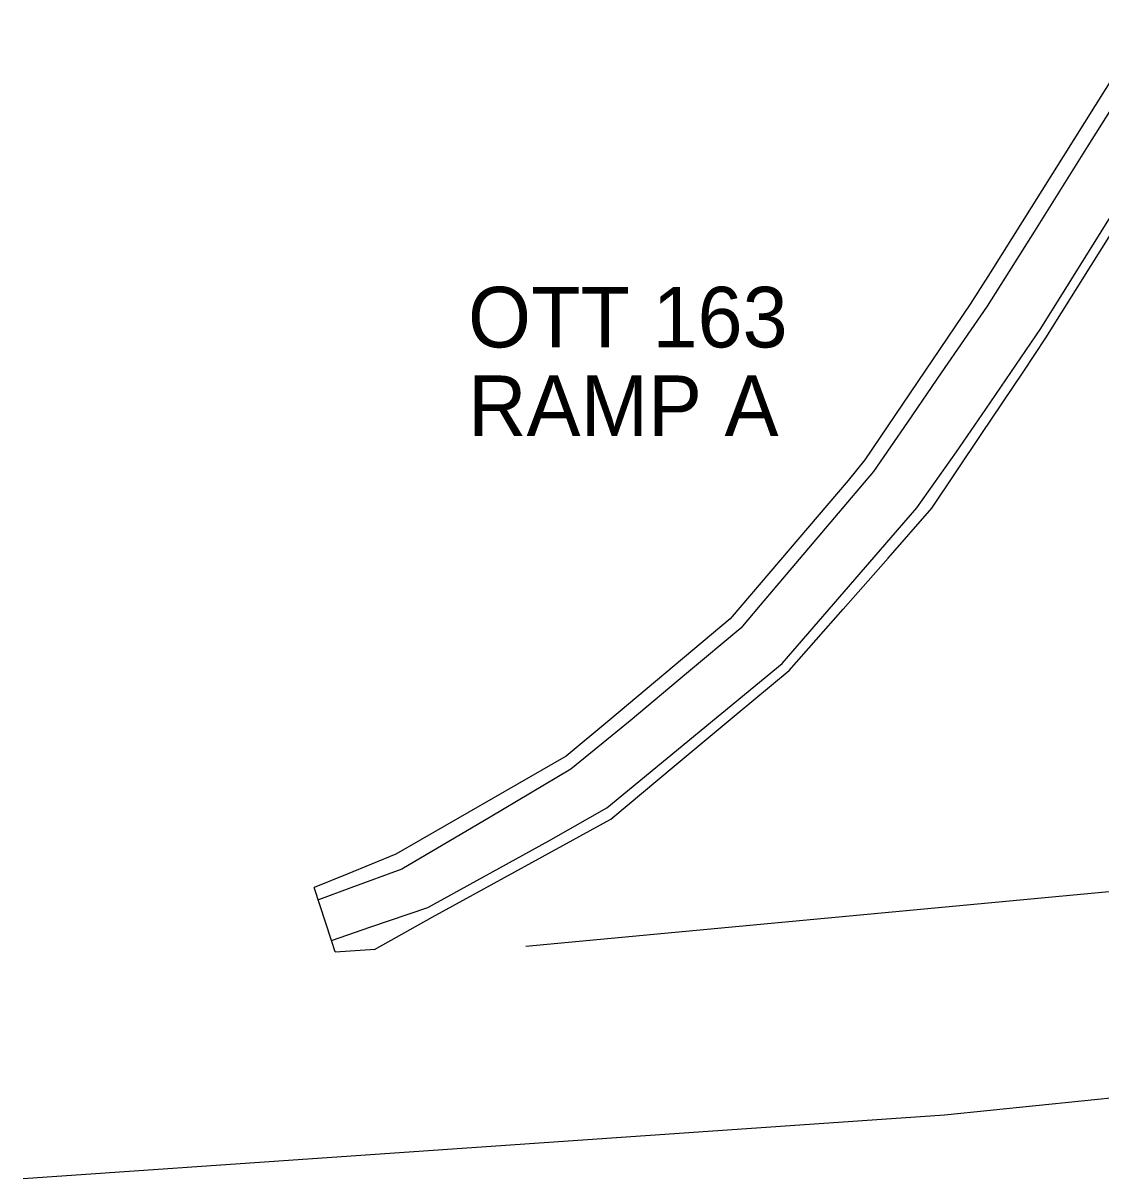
# Model space of a CAD drawing. Extents: x 1855721 to 1876784, y 662259 to 674089.
# Drawn here: x 1855720.9 to 1856041.2, y 673599.2 to 673942.7 of the extents above; entities that cross this region are included whole.
import ezdxf

# ---------------------------------------------------------------- set-up
doc = ezdxf.new("R2010")
doc.units = 0
for name, color, linetype in [('_CIVIL_CONSTRUCTION', 7, 'Continuous'), ('GE_X_Alignment_100_Cardinal_Points', 7, 'Continuous'), ('GE_X_Alignment_100_Curve_Data', 7, 'Continuous'), ('PV_X_EOP', 7, 'Continuous'), ('SC_Scratch1', 7, 'Continuous')]:
    doc.layers.add(name, color=color, linetype=linetype)

msp = doc.modelspace()

# ---------------------------------------------------------------- linework, layer by layer
at = {"layer": '_CIVIL_CONSTRUCTION'}
msp.add_line((1855812.58, 673670.09), (1855807.47, 673685.82), dxfattribs=at)
msp.add_lwpolyline([(1856050.21, 673926.63), (1856037.35, 673906.18), (1856021.45, 673880.88), (1856007.43, 673858.57), (1855993.79, 673838.7), (1855983.77, 673824.12), (1855973.68, 673809.44), (1855958.23, 673791.21), (1855939.99, 673769.68), (1855934.24, 673762.89), (1855918.07, 673749.37), (1855901.32, 673735.36), (1855883.71, 673720.96), (1855859.75, 673706.75), (1855833.5, 673691.31), (1855818.35, 673685.7), (1855808.67, 673682.11)], dxfattribs=at)
at = {"layer": 'GE_X_Alignment_100_Cardinal_Points'}
msp.add_line((1855812.58, 673670.09), (1855824.3, 673674.09), dxfattribs=at)
at = {"layer": 'GE_X_Alignment_100_Curve_Data'}
msp.add_lwpolyline([(1855824.3, 673674.09), (1855841.18, 673679.85), (1855877.15, 673699.72), (1855894.42, 673709.44), (1855946.54, 673752.34), (1855986.53, 673798.61), (1855998.27, 673815.29), (1856007.02, 673827.98), (1856023.41, 673851.89), (1856068.46, 673924.1)], dxfattribs=at)
at = {"layer": 'PV_X_EOP'}
msp.add_line((1855870.31, 673668.36), (1856166.87, 673696.18), dxfattribs=at)
msp.add_lwpolyline([(1856239.02, 673643.09), (1855994.72, 673618.12), (1855720.93, 673599.23)], dxfattribs=at)
at = {"layer": 'SC_Scratch1'}
for q in [(1855812.58, 673670.09), (1855825.58, 673667.52)]:
    msp.add_line((1855813.7, 673666.65), q, dxfattribs=at)
for points in [[(1856054.88, 673942.67), (1856008.34, 673868.46), (1856002.39, 673859.11), (1855971.11, 673812.92), (1855966.15, 673806.78), (1855931.02, 673765.63), (1855895.28, 673735.62), (1855882.36, 673724.83), (1855831.72, 673695.74), (1855817.21, 673689.8), (1855807.47, 673685.82)], [(1855825.35, 673667.39), (1855842.47, 673676.97), (1855864.02, 673688.81), (1855875.14, 673694.91), (1855895.6, 673706.15), (1855914.42, 673721.85), (1855932.84, 673737.21), (1855948.57, 673750.33), (1855964.66, 673768.55), (1855977.99, 673783.64), (1855990.96, 673798.51), (1856005.66, 673820.43), (1856018.28, 673839.24), (1856024.89, 673849.12), (1856038.34, 673870.6), (1856053.86, 673895.4)]]:
    msp.add_lwpolyline(points, dxfattribs=at)

# ---------------------------------------------------------------- texts
for s, p in [('OTT 163', (1855853.15, 673846.3)), ('RAMP A', (1855853.15, 673819.96))]:
    msp.add_text(s, height=18, dxfattribs=at).set_placement(p)

doc.saveas('drawing.dxf')
